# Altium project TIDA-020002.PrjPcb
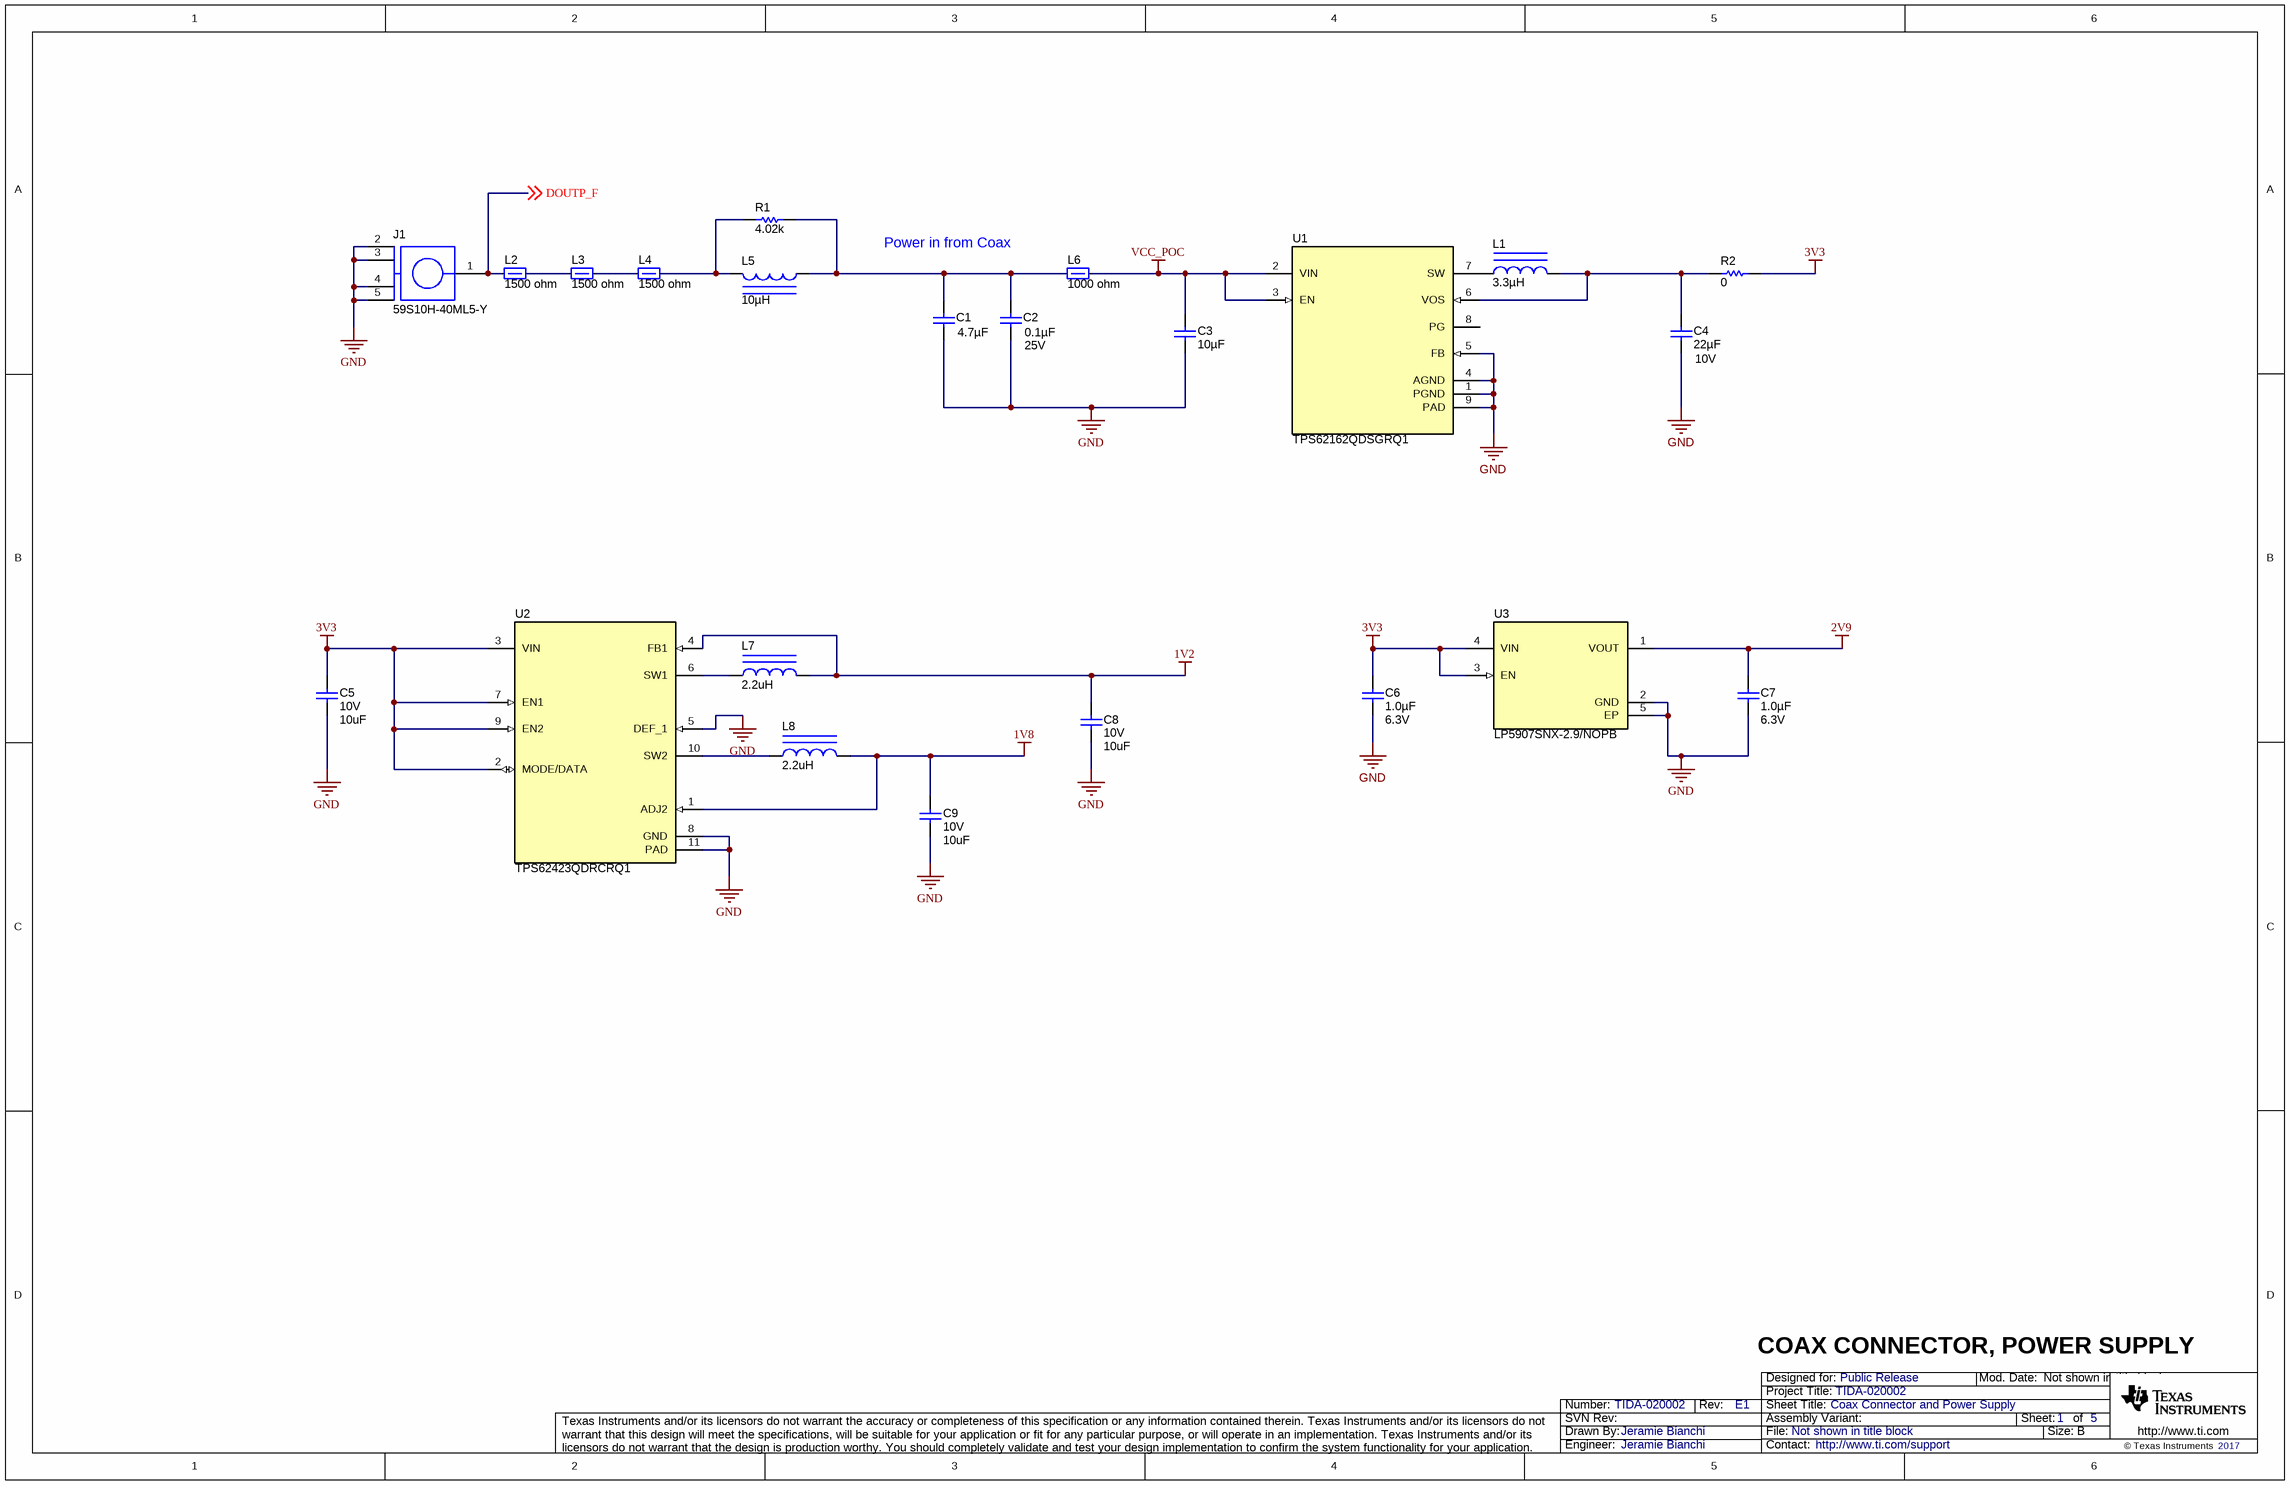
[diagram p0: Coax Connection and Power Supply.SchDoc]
TechSupport: http://www.ti.com/support; SCH_Rev: E1; PRJ_Title: TIDA-020002; PRJ_Number: TIDA-020002; PRJ_Engineer: Jeramie Bianchi; PRJ_Customer: Public Release; PCB_Rev: E1; PCB_Layout: Jeramie Bianchi; CopyrightYear: 2017
5 sheets, 104 parts. Net scope: global (net labels, ports and power ports of the same name join across sheets).
Board file: TIDA-020002.PcbDoc
Sheets:
  Coax Connection and Power Supply.SchDoc
  Imager.SchDoc
  Serializer.SchDoc
  HDWR.SchDoc
  Voltage Supervision.SchDoc

## Sheet Coax Connection and Power Supply.SchDoc: Coax Connector and Power Supply
size 431 x 279 mm; Date: Not shown in title block; ApprovedBy: Not shown in title block; CheckedBy: Not shown in title block; Author: Not shown in title block; CompanyName: Not shown in title block; DrawnBy: Jeramie Bianchi; Engineer: Not shown in title block; Organization: Not shown in title block; Address1: Not shown in title block; Address2: Not shown in title block; Address3: Not shown in title block; Address4: Not shown in title block; DocumentNumber: 1; Revision: Use project parameter SCH_Rev; SheetNumber: 1; SheetTotal: 5; PageSetup: Record=PageOptions¦CenterHorizontal=True¦CenterVertical=True¦PrintScale=0.62¦XCorrection=1.00¦YCorrection=1.00¦PrintKind=0¦BorderSize=5000000¦LeftOffset=0¦BottomOffset=0¦Orientation=2¦PaperLength=1000¦PaperWidth=1000¦Scale=100¦PaperSource=15¦PrintQuality=600¦MediaType=1¦DitherType=10¦PrintScaleMode=1¦PaperKind=Letter (8.5 x 11")¦PaperIndex=1

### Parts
C1  value 4.7µF  [0805L]  (hidden comment: CGA4J1X7R1E475M125AC)
C2  value 0.1µF  VDC_V: 25V  [0402L]  (hidden comment: C1005X7R1E104K050BB)
C3  ValueDisplayed: 10µF  [1206_190]  (hidden comment: C3216X7R1E106M160AE)
C4  ValueDisplayed: 22µF  VDC_V: 10V  [1206L]  (hidden comment: GRM31CR71A226KE15L)
C5  VDC_V: 10V  ValueDisplayed: 10uF  [0603S]  (hidden comment: GRM188Z71A106MA73D)
C6  value 1.0µF  VDC_V: 6.3V  [0402L]  (hidden comment: CL05B105KQ5NQNC)
C7  value 1.0µF  VDC_V: 6.3V  [0402L]  (hidden comment: CL05B105KQ5NQNC)
C8  VDC_V: 10V  ValueDisplayed: 10uF  [0603S]  (hidden comment: GRM188Z71A106MA73D)
C9  VDC_V: 10V  ValueDisplayed: 10uF  [0603S]  (hidden comment: GRM188Z71A106MA73D)
J1  59S10H-40ML5-Y  [59S10H-40ML5-Y]
L1  ValueDisplayed: 3.3µH  [XPL2010]  (hidden comment: XPL2010-332MLB)
L2  value 1500 ohm  [0603L]  (hidden comment: BLM18HE152SN1D)
L3  value 1500 ohm  [0603L]  (hidden comment: BLM18HE152SN1D)
L4  value 1500 ohm  [0603L]  (hidden comment: BLM18HE152SN1D)
L5  ValueDisplayed: 10µH  [LQH3NPZ_JR]  (hidden comment: LQH3NPZ100MJRL)
L6  value 1000 ohm  [0603L]  (hidden comment: BLM18AG102SN1D)
L7  ValueDisplayed: 2.2uH  [LQM2MPN_G0]  (hidden comment: LQM2MPN2R2NG0)
L8  ValueDisplayed: 2.2uH  [LQM2MPN_G0]  (hidden comment: LQM2MPN2R2NG0)
R1  ValueDisplayed: 4.02k  [0603L]  (hidden comment: CRCW06034K02FKEA)
R2  value 0  [0402S]  (hidden comment: CRCW04020000Z0ED)
U1  TPS62162QDSGRQ1  [DSG0008A]
U2  TPS62423QDRCRQ1  [DRC0010J]
U3  LP5907SNX-2.9/NOPB  [DQN0004A]

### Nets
1V2: C8.1 L7.2 U2.4(FB1)
1V8: C9.1 L8.2 U2.1(ADJ2)
2V9: C7.1 U3.1(VOUT)
3V3: C5.1 C6.1 R2.1 U2.2(MODE/DATA) U2.3(VIN) U2.7(EN1) U2.9(EN2) U3.3(EN) U3.4(VIN)
GND: C1.2 C2.2 C3.2 C4.2 C5.2 C6.2 C7.2 C8.2 C9.2 J1.2 J1.3 J1.4 J1.5 U1.1(PGND) U1.4(AGND) U1.5(FB) U1.9(PAD) U2.5(DEF_1) U2.8(GND) U2.11(PAD) U3.2(GND) U3.5(EP)
VCC_POC: C3.1 L6.2 U1.2(VIN) U1.3(EN)
DOUTP_F: J1.1 L2.1 ; off-sheet DOUTP_F
NetC1_1: C1.1 C2.1 L5.1 L6.1 R1.1
NetC4_1: C4.1 L1.2 R2.2 U1.6(VOS)
NetL1_1: L1.1 U1.7(SW)
NetL2_2: L2.2 L3.1
NetL3_2: L3.2 L4.1
NetL4_2: L4.2 L5.2 R1.2
NetL7_1: L7.1 U2.6(SW1)
NetL8_1: L8.1 U2.10(SW2)

Not connected (* = marked no-connect by the designer): U1 8(PG)

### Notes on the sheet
- (near L6) Power in from Coax
- COAX CONNECTOR, POWER SUPPLY

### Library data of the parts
C1 = C2012X7R1E474K: CAP, CERM, 4.7uF, 25V, +/-20%, X7R, 0805; Manufacturer: TDK Corporation; Tolerance_%: ±20%
C2 = C1005X7R1E103K: CAP, CERM, 0.1uF, 25V, +/-10%, X7R, 0402; Manufacturer: TDK Corporation; Tolerance_%: ±10%
C3 = C3216X7R1E106M160AE: CAP, CERM, 10 µF, 25 V,+/- 20%, X7R, 1206; Manufacturer: TDK; Polarized: N; CompType: Capacitor; Value: 10uF; U/M: EA; Cap_F: 0.00001; Tolerance_%: 20; VDC_V: 25; Value2: 25V; TaMin_C: -55; TaMax_C: 125; Cap_Case: 1206; SizeArea_mm2: 5.12; SizeAreaWB_mm2: 10.92; SizeX_mm: 3.2; SizeY_mm: 1.6; SizeZ_mm: 1.9; AEC Category: Q200; Green_Lifecycle: Active; Green_REACh: Passed
C4 = GRM31CR71A226KE15L: CAP, CERM, 22uF, 10V, +/-10%, X7R, 1206; Manufacturer: MuRata; Polarized: N; CompType: Capacitor; U/M: EA; Cap_F: 0.000022; Tolerance_%: 10; Value1: Unknown; TaMin_C: -55; TaMax_C: 125; Cap_Case: 1206
C5 C8 C9 = CMP-0007497-5: CAP, CERM, 10 uF, 10 V, +/- 20%, X7R, 0603; Manufacturer: MuRata; TaMin_C: -55°C; Polarized: N; SizeAreaWB_mm2: 4.68; Value1: Unknown; U/M: EA; Value: 10uF; TaMax_C: 125°C; SizeZ_mm: 1; SizeX_mm: 1.6; SizeY_mm: 0.8; Cap_Case: 0603; SizeArea_mm2: 1.28; CompType: Capacitor; Cap_F: 10µF; AEC Category: Q200
C6 C7 = Capacitor: CAP CER 1UF 6.3V 10% X7R 0402; Manufacturer: Samsung Electro-Mechanics America, Inc; Polarized: N; U/M: EA
J1 = 59S10H-40ML5-Y: Straight Plug PCB; Manufacturer: Rosenberger; SymbolVersion: use current date i.e. 2008-05-20; SymbolCreator: Use a-id; CompType: SMA connector; U/M: EA, IN, or GM
L1 = XPL2010-332MLB: Inductor, Shielded, Composite, 3.3 µH, 1.05 A, 0.21 ohm, SMD; Manufacturer: Coilcraft; Value: 3.3uH; Ind_H: 3.3E-6; Imax_A: 1.05; Irms: 1.1A @ 40C rise; Isat: 1.05A @ 30% inductance drop; DCR_ohm: 0.21; Value2: 1.05A; SizeAreaWB_mm2: 8.7; SizeArea_mm2: 3.8; SizeX_mm: 2; SizeY_mm: 1.9; SizeZ_mm: 1; AEC Category: Q200; Green_Lifecycle: Not Set; Green_REACh: Incomplete
L2 L3 = BLM18HE152SN1D: Ferrite Bead, 1500 ohm @ 100 MHz, 0.5 A, 0603; Manufacturer: MuRata; Imax_A: 0.5; Value1: 0.5 ohm; Value2: 0.5A; ZTyp@100MHz_Ohm: 1500; SizeAreaWB_mm2: 4.68; SizeArea_mm2: 1.28; SizeX_mm: 1.6; SizeY_mm: 0.8; SizeZ_mm: 1
L4 = BLM18HE152SN1D: Ferrite Bead, 1500 ohm @ 100 MHz, 0.5 A, 0603; Manufacturer: MuRata; Value1: 0.5 ohm; Value2: 0.5A; SizeArea_mm2: 1.28; SizeX_mm: 1.6; SizeY_mm: 0.8; SizeZ_mm: 1; Imax_A: 0.5; SizeAreaWB_mm2: 4.68; ZTyp@100MHz_Ohm: 1500
L5 = LQH3NPZ100MJRL: Inductor, Wirewound, Ferrite, 10 µH, 0.81 A, 0.288 ohm, AEC-Q200 Grade 1, SMD; Manufacturer: MuRata; Value: 10uH; Ind_H: 10.0E-6; Imax_A: 0.81; Irms: 1.2A @ 40C rise; Isat: 0.81A @ 30% inductance drop; DCR_ohm: 0.288; Value2: 0.81A; SizeAreaWB_mm2: 16; SizeArea_mm2: 9; SizeX_mm: 3; SizeZ_mm: 1.2; AEC Category: Q200; AEC Qualified: Y; AEC Grade: 1
L6 = BLM18AG102SN1D: Ferrite Bead, 1000 ohm @ 100 MHz, 0.4 A, 0603; Manufacturer: MuRata; Imax_A: 0.4; DCR_ohm: 0.5; Value1: 0.5 ohm; Value2: 0.4A; ZTyp@100MHz_Ohm: 1000
L7 L8 = CMP-0058761-1: Inductor, Multilayer, Ferrite, 2.2 uH, 1.2 A, 0.11 ohm, SMD; Manufacturer: MuRata; Irms: 1.2A @ 40C rise; SizeAreaWB_mm2: 7.8; DCR_ohm: 1.1d; Value: 2.2uH; Imax_A: 1.2A; SizeZ_mm: 1; SizeX_mm: 2; SizeY_mm: 1.6; SizeArea_mm2: 3.2; Ind_H: 2.2µH; AEC Qualified: N; AEC Category: Q200
R1 = CRCW06034K02FKEA: RES, 4.02 k, 1%, 0.1 W, 0603; Manufacturer: Vishay-Dale; CompType: Resistor; Value: 4.02k; Res_ohm: 4020; Value_Code: 4k02; Tolerance_%: 1; Power_W: 0.1; Value2: 0.1W; VDC_V: 75; TempCo: 100 ppm/C; EIA_Code: E96; U/M: EA
R2 = CRCW04020000Z0ED: RES, 0 ohm, 5%, 0.063W, 0402; Manufacturer: Vishay-Dale; CompType: Resistor; Value_Code: 0000; Tolerance_%: 5; Power_W: 0.063; VDC_V: 50; TempCo: 200 ppm/C; EIA_Code: E24; U/M: EA
U1 = TPS62162QDSGRQ1: 3V-17V 1A Automotive Step-Down Converters in 2x2SON, DSG0008A (WSON-8); Manufacturer: Texas Instruments; Alternate PartNumber: TPS62162QDSGTQ1; SymbolCreator: Altium; SizeArea_mm2: 4; SizeAreaWB_mm2: 9; SizeX_mm: 2; SizeZ_mm: 0.8; CompType: IC; U/M: EA
U2 = CMP-0074043-2: Automotive 2.5V to 6V, 2.25MHz Fixed Frequency Dual (800mA/800mA) Buck Converter, DRC0010J (VSON-10); Alternate Manufacturer: Texas Instruments; Green_Lifecycle: Active; SizeAreaWB_mm2: 16.0; Green_REACh: Passed; U/M: EA; SizeZ_mm: 1.0; SizeX_mm: 3.0; SizeArea_mm2: 9.0; CompType: IC
U3 = CMP-0066023-1: 250-mA Ultra-Low-Noise, Low-IQ LDO, DQN0004A (X2SON-4); Alternate Manufacturer: Texas Instruments; SizeAreaWB_mm2: 4.0; U/M: EA; SizeZ_mm: 0.4; SizeX_mm: 1.0; CompType: IC

## Sheet Imager.SchDoc: Image Sensor
size 431 x 279 mm; Date: Not shown in title block; ApprovedBy: Not shown in title block; CheckedBy: Not shown in title block; Author: Not shown in title block; CompanyName: Not shown in title block; DrawnBy: Jeramie Bianchi; Engineer: Not shown in title block; Organization: Not shown in title block; Address1: Not shown in title block; Address2: Not shown in title block; Address3: Not shown in title block; Address4: Not shown in title block; DocumentNumber: 2; Revision: Use project parameter SCH_Rev; SheetNumber: 3; SheetTotal: 5; PageSetup: Record=PageOptions¦CenterHorizontal=True¦CenterVertical=True¦PrintScale=0.96¦XCorrection=1.00¦YCorrection=1.00¦PrintKind=0¦BorderSize=5000000¦LeftOffset=0¦BottomOffset=0¦Orientation=2¦PaperLength=4318¦PaperWidth=2794¦Scale=100¦PaperSource=15¦PrintQuality=600¦MediaType=1¦DitherType=10¦PrintScaleMode=1¦PaperKind=Tabloid (11 x 17")¦PaperIndex=17
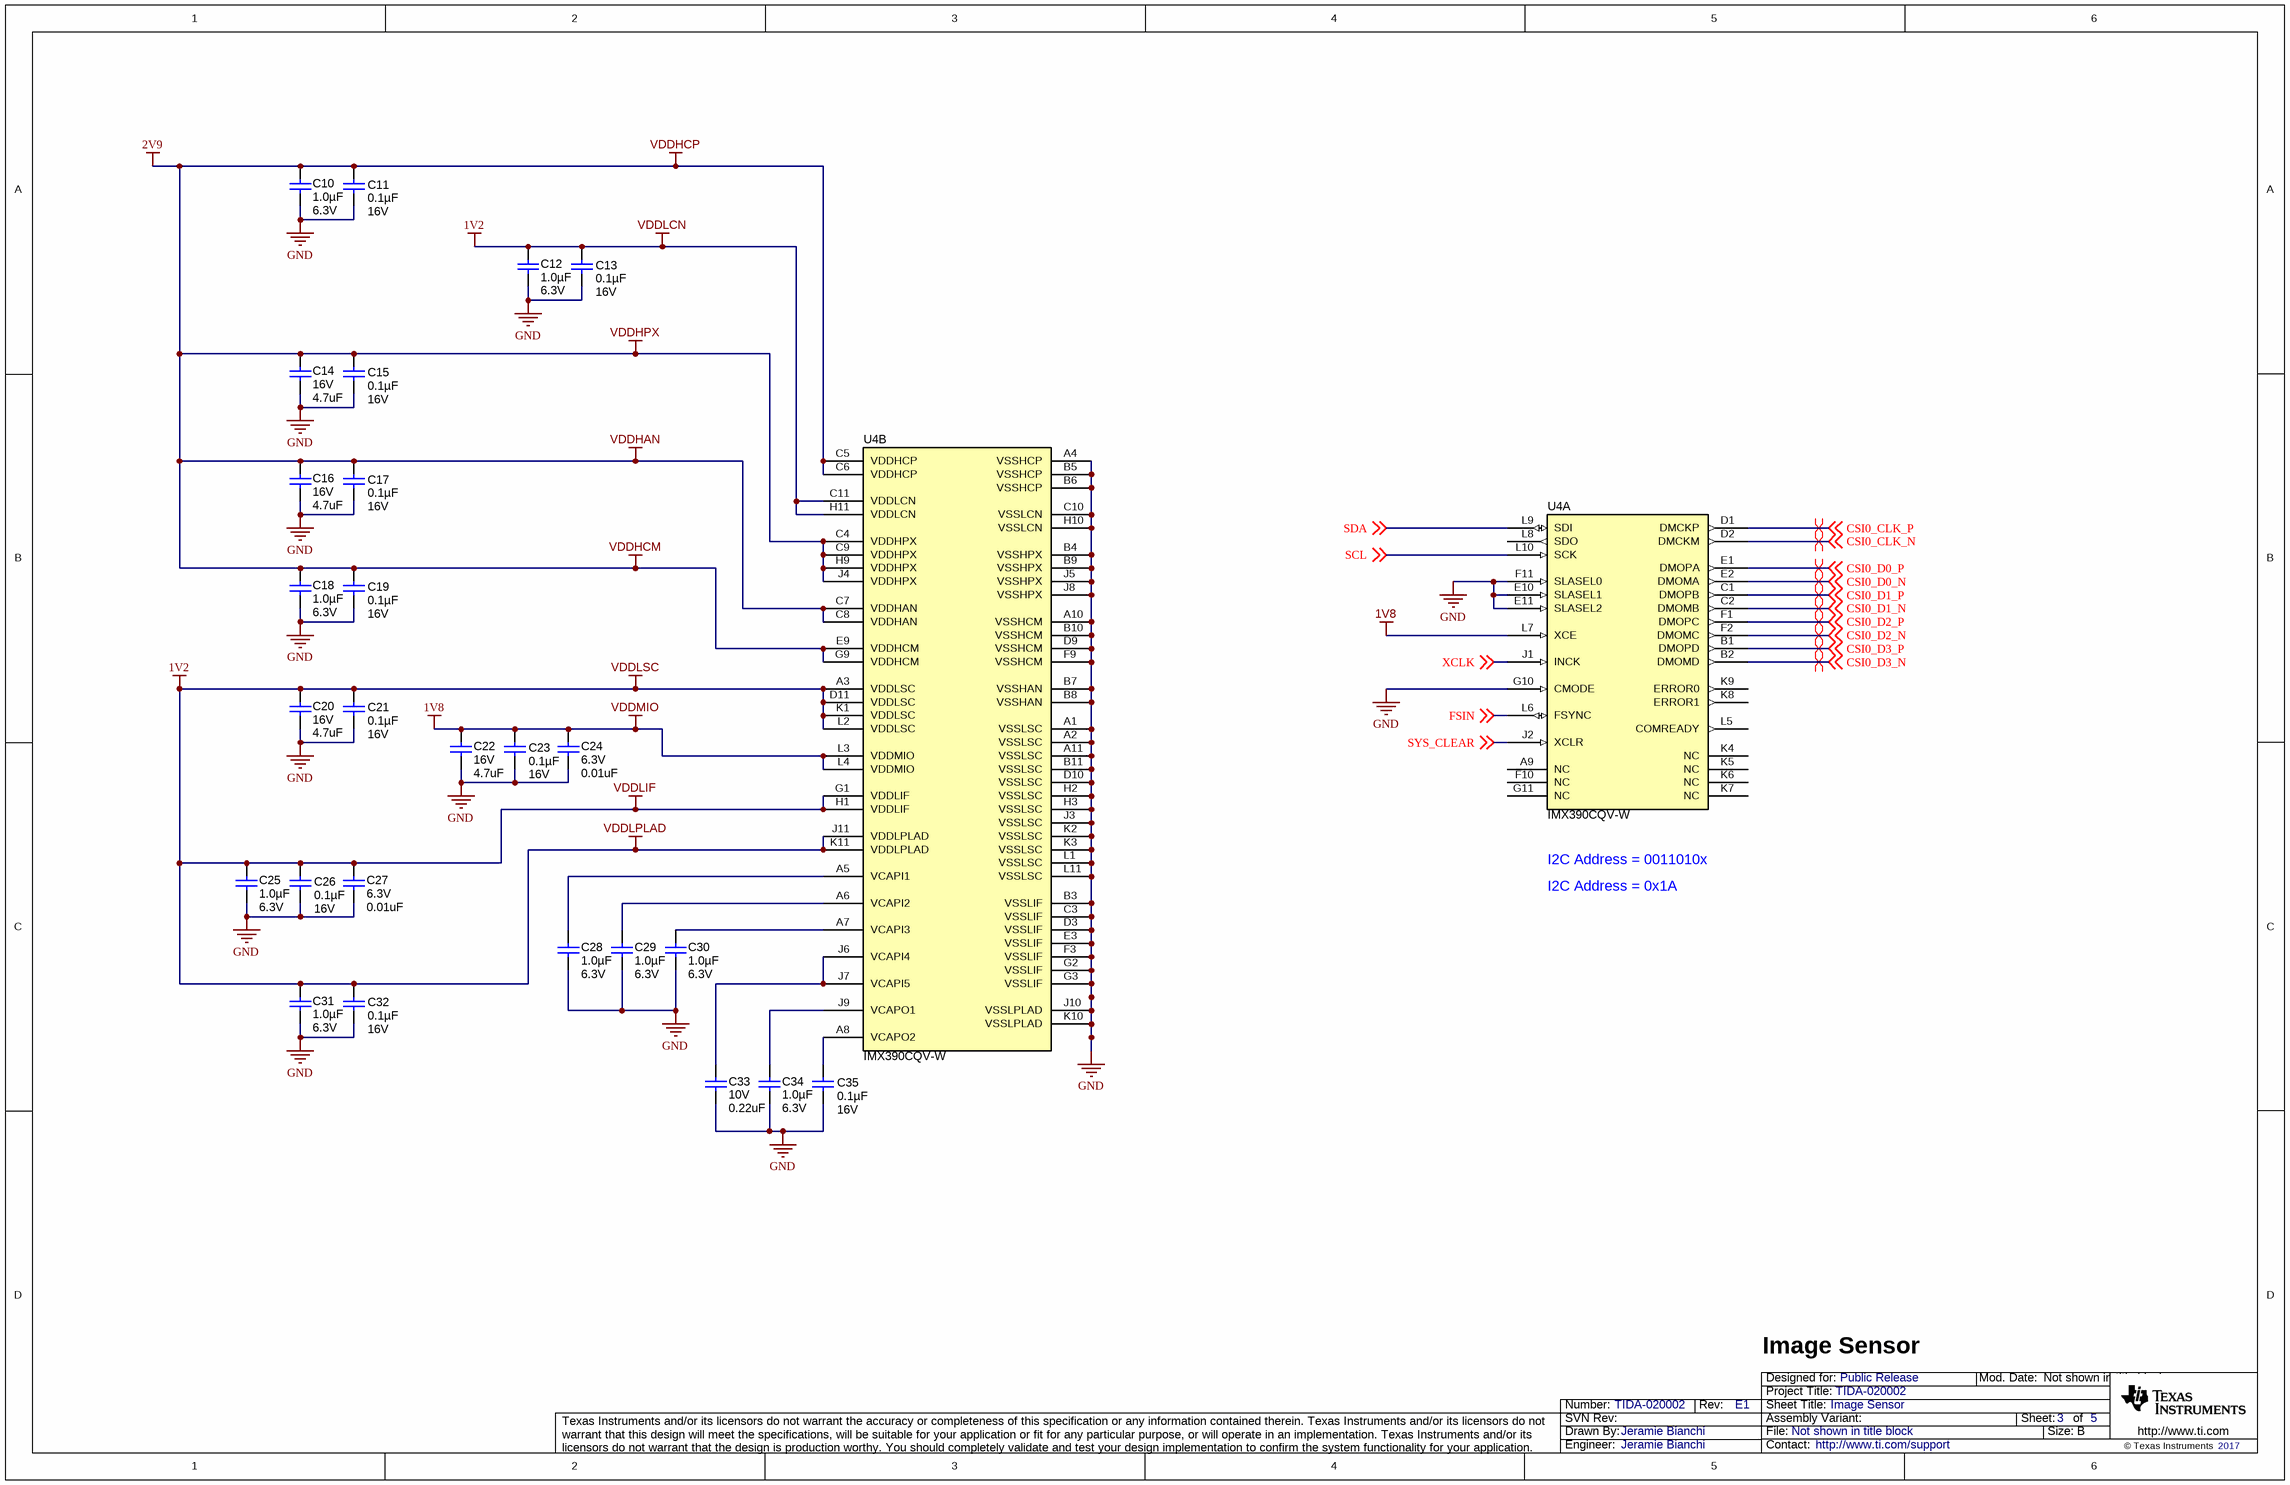
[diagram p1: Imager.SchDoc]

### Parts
C10  value 1.0µF  VDC_V: 6.3V  [0402L]  (hidden comment: CL05B105KQ5NQNC)
C11  ValueDisplayed: 0.1µF  Value2: 16V  [0402S]  (hidden comment: 0402YC104KAT2A)
C12  value 1.0µF  VDC_V: 6.3V  [0402L]  (hidden comment: CL05B105KQ5NQNC)
C13  ValueDisplayed: 0.1µF  Value2: 16V  [0402S]  (hidden comment: 0402YC104KAT2A)
C14  VDC_V: 16V  ValueDisplayed: 4.7uF  [0603S]  (hidden comment: GRM188Z71C475KE21D)
C15  ValueDisplayed: 0.1µF  Value2: 16V  [0402S]  (hidden comment: 0402YC104KAT2A)
C16  VDC_V: 16V  ValueDisplayed: 4.7uF  [0603S]  (hidden comment: GRM188Z71C475KE21D)
C17  ValueDisplayed: 0.1µF  Value2: 16V  [0402S]  (hidden comment: 0402YC104KAT2A)
C18  value 1.0µF  VDC_V: 6.3V  [0402L]  (hidden comment: CL05B105KQ5NQNC)
C19  ValueDisplayed: 0.1µF  Value2: 16V  [0402S]  (hidden comment: 0402YC104KAT2A)
C20  VDC_V: 16V  ValueDisplayed: 4.7uF  [0603S]  (hidden comment: GRM188Z71C475KE21D)
C21  ValueDisplayed: 0.1µF  Value2: 16V  [0402S]  (hidden comment: 0402YC104KAT2A)
C22  VDC_V: 16V  ValueDisplayed: 4.7uF  [0603S]  (hidden comment: GRM188Z71C475KE21D)
C23  ValueDisplayed: 0.1µF  Value2: 16V  [0402S]  (hidden comment: 0402YC104KAT2A)
C24  VDC_V: 6.3V  ValueDisplayed: 0.01uF  [0402S]  (hidden comment: GRM155R70J103KA01D)
C25  value 1.0µF  VDC_V: 6.3V  [0402L]  (hidden comment: CL05B105KQ5NQNC)
C26  ValueDisplayed: 0.1µF  Value2: 16V  [0402S]  (hidden comment: 0402YC104KAT2A)
C27  VDC_V: 6.3V  ValueDisplayed: 0.01uF  [0402S]  (hidden comment: GRM155R70J103KA01D)
C28  value 1.0µF  VDC_V: 6.3V  [0402L]  (hidden comment: CL05B105KQ5NQNC)
C29  value 1.0µF  VDC_V: 6.3V  [0402L]  (hidden comment: CL05B105KQ5NQNC)
C30  value 1.0µF  VDC_V: 6.3V  [0402L]  (hidden comment: CL05B105KQ5NQNC)
C31  value 1.0µF  VDC_V: 6.3V  [0402L]  (hidden comment: CL05B105KQ5NQNC)
C32  ValueDisplayed: 0.1µF  Value2: 16V  [0402S]  (hidden comment: 0402YC104KAT2A)
C33  VDC_V: 10V  ValueDisplayed: 0.22uF  [0402S]  (hidden comment: GRM155R71A224KE01D)
C34  value 1.0µF  VDC_V: 6.3V  [0402L]  (hidden comment: CL05B105KQ5NQNC)
C35  ValueDisplayed: 0.1µF  Value2: 16V  [0402S]  (hidden comment: 0402YC104KAT2A)
U4  IMX390CQV-W  [BGA-96]  (parts A,B of 2)

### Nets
1V2: C12.1 C13.1 C20.1 C21.1 C25.1 C26.1 C27.1 C31.1 C32.1 U4.A3(VDDLSC) U4.C11(VDDLCN) U4.D11(VDDLSC) U4.G1(VDDLIF) U4.H1(VDDLIF) U4.H11(VDDLCN) U4.J11(VDDLPLAD) U4.K1(VDDLSC) U4.K11(VDDLPLAD) U4.L2(VDDLSC)  [also labelled VDDLCN, VDDLIF, VDDLPLAD, VDDLSC]
1V8: C22.1 C23.1 C24.1 U4.L3(VDDMIO) U4.L4(VDDMIO) U4.L7(XCE)  [also labelled VDDMIO]
2V9: C10.1 C11.1 C14.1 C15.1 C16.1 C17.1 C18.1 C19.1 U4.C4(VDDHPX) U4.C5(VDDHCP) U4.C6(VDDHCP) U4.C7(VDDHAN) U4.C8(VDDHAN) U4.C9(VDDHPX) U4.E9(VDDHCM) U4.G9(VDDHCM) U4.H9(VDDHPX) U4.J4(VDDHPX)  [also labelled VDDHAN, VDDHCM, VDDHCP, VDDHPX]
GND: C10.2 C11.2 C12.2 C13.2 C14.2 C15.2 C16.2 C17.2 C18.2 C19.2 C20.2 C21.2 C22.2 C23.2 C24.2 C25.2 C26.2 C27.2 C28.2 C29.2 C30.2 C31.2 C32.2 C33.2 C34.2 C35.2 U4.A1(VSSLSC) U4.A2(VSSLSC) U4.A4(VSSHCP) U4.A10(VSSHCM) U4.A11(VSSLSC) U4.B3(VSSLIF) U4.B4(VSSHPX) U4.B5(VSSHCP) U4.B6(VSSHCP) U4.B7(VSSHAN) U4.B8(VSSHAN) U4.B9(VSSHPX) U4.B10(VSSHCM) U4.B11(VSSLSC) U4.C3(VSSLIF) U4.C10(VSSLCN) U4.D3(VSSLIF) U4.D9(VSSHCM) U4.D10(VSSLSC) U4.E3(VSSLIF) U4.E10(SLASEL1) U4.E11(SLASEL2) U4.F3(VSSLIF) U4.F9(VSSHCM) U4.F11(SLASEL0) U4.G2(VSSLIF) U4.G3(VSSLIF) U4.G10(CMODE) U4.H2(VSSLSC) U4.H3(VSSLSC) U4.H10(VSSLCN) U4.J3(VSSLSC) U4.J5(VSSHPX) U4.J8(VSSHPX) U4.J10(VSSLPLAD) U4.K2(VSSLSC) U4.K3(VSSLSC) U4.K10(VSSLPLAD) U4.L1(VSSLSC) U4.L11(VSSLSC)
CSI0_CLK_N: U4.D2(DMCKM) ; off-sheet CSI0_CLK_N
CSI0_CLK_P: U4.D1(DMCKP) ; off-sheet CSI0_CLK_P
CSI0_D0_N: U4.E2(DMOMA) ; off-sheet CSI0_D0_N
CSI0_D0_P: U4.E1(DMOPA) ; off-sheet CSI0_D0_P
CSI0_D1_N: U4.C2(DMOMB) ; off-sheet CSI0_D1_N
CSI0_D1_P: U4.C1(DMOPB) ; off-sheet CSI0_D1_P
CSI0_D2_N: U4.F2(DMOMC) ; off-sheet CSI0_D2_N
CSI0_D2_P: U4.F1(DMOPC) ; off-sheet CSI0_D2_P
CSI0_D3_N: U4.B2(DMOMD) ; off-sheet CSI0_D3_N
CSI0_D3_P: U4.B1(DMOPD) ; off-sheet CSI0_D3_P
FSIN: U4.L6(FSYNC) ; off-sheet FSIN
SCL: U4.L10(SCK) ; off-sheet SCL
SDA: U4.L9(SDI) ; off-sheet SDA
SYS_CLEAR: U4.J2(XCLR) ; off-sheet SYS_CLEAR
XCLK: U4.J1(INCK) ; off-sheet XCLK
NetC28_1: C28.1 U4.A5(VCAPI1)
NetC29_1: C29.1 U4.A6(VCAPI2)
NetC30_1: C30.1 U4.A7(VCAPI3)
NetC33_1: C33.1 U4.J6(VCAPI4) U4.J7(VCAPI5)
NetC34_1: C34.1 U4.J9(VCAPO1)
NetC35_1: C35.1 U4.A8(VCAPO2)

Not connected (* = marked no-connect by the designer): U4 A9(NC) F10(NC) G11(NC) K4(NC) K5(NC) K6(NC) K7(NC) K8(ERROR1) K9(ERROR0) L5(COMREADY) L8(SDO)

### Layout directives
differential pair: CSI0_CLK_N, CSI0_CLK_P, CSI0_D0_N, CSI0_D0_P, CSI0_D1_N, CSI0_D1_P, CSI0_D2_N, CSI0_D2_P, CSI0_D3_N, CSI0_D3_P

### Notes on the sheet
- I2C Address = 0011010x
- I2C Address = 0x1A
- Image Sensor

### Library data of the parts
C10 C12 C18 C25 C28-C31 C34 = Capacitor: as C6 on sheet Coax Connection and Power Supply
C11 C13 C15 C17 C19 C21 C23 C26 C32 C35 = 0402YC104KAT2A: CAP, CERM, 0.1 µF, 16 V, +/- 10%, X7R, 0402; Manufacturer: AVX; Polarized: N; CompType: Capacitor; Value: 0.1uF; U/M: EA; Cap_F: 0.0000001; Tolerance_%: 10; Value1: Unknown; VDC_V: 16; TaMin_C: -55; TaMax_C: 125; Cap_Case: 0402; SizeArea_mm2: 0.5; SizeAreaWB_mm2: 3; SizeX_mm: 1; SizeZ_mm: 0.6; AEC Category: Q200
C14 C16 C20 C22 = CMP-0064936-4: CAP, CERM, 4.7 uF, 16 V,+/- 10%, X7R, 0603; Manufacturer: MuRata; TaMin_C: -55°C; Polarized: N; SizeAreaWB_mm2: 4.68; Value1: Unknown; U/M: EA; Value: 4.7uF; TaMax_C: 125°C; SizeZ_mm: 1; SizeX_mm: 1.6; SizeY_mm: 0.8; Cap_Case: 0603; SizeArea_mm2: 1.28; CompType: Capacitor; Cap_F: 4.7µF; AEC Category: Q200
C24 C27 = CMP-0006622-2: CAP, CERM, 0.01 uF, 6.3 V, +/- 10%, X7R, 0402; Manufacturer: MuRata; TaMin_C: -55°C; Polarized: N; SizeAreaWB_mm2: 3; Value1: Unknown; U/M: EA; Value: 0.01uF; TaMax_C: 125°C; SizeZ_mm: 0.6; SizeX_mm: 1; SizeY_mm: 0.5; Cap_Case: 0402; CompType: Capacitor; Cap_F: 10nF; AEC Category: Q200
C33 = CMP-0006630-2: CAP, CERM, 0.22 uF, 10 V, +/- 10%, X7R, 0402; Manufacturer: MuRata; TaMin_C: -55°C; Polarized: N; SizeAreaWB_mm2: 3; Value1: Unknown; U/M: EA; Value: 0.22uF; TaMax_C: 125°C; SizeZ_mm: 0.6; SizeX_mm: 1; SizeY_mm: 0.5; Cap_Case: 0402; CompType: Capacitor; Cap_F: 220nF; AEC Category: Q200
U4 = CMP-0078540-1: Diagonal 6.67mm (Type 1/2.7) CMOS Solid-sate Image Sensor with Square Pixel and RGGB Filter Array, BGA-96; Manufacturer: Sony; SizeArea_mm2: 106; SizeAreaWB_mm2: 151.2; SizeY_mm: 10; SizeZ_mm: 1.6; SizeX_mm: 10.6

## Sheet Serializer.SchDoc: Serializer
size 431 x 279 mm; Date: Not shown in title block; ApprovedBy: Not shown in title block; CheckedBy: Not shown in title block; Author: Not shown in title block; CompanyName: Not shown in title block; DrawnBy: Jeramie Bianchi; Engineer: Not shown in title block; Organization: Not shown in title block; Address1: Not shown in title block; Address2: Not shown in title block; Address3: Not shown in title block; Address4: Not shown in title block; DocumentNumber: 3; Revision: Use project parameter SCH_Rev; SheetNumber: 4; SheetTotal: 5; PageSetup: Record=PageOptions¦CenterHorizontal=True¦CenterVertical=True¦PrintScale=0.64¦XCorrection=1.00¦YCorrection=1.00¦PrintKind=0¦BorderSize=5000000¦LeftOffset=0¦BottomOffset=0¦Orientation=2¦PaperLength=4318¦PaperWidth=2794¦Scale=100¦PaperSource=15¦PrintQuality=600¦MediaType=1¦DitherType=10¦PrintScaleMode=1¦PaperKind=Tabloid (11 x 17")¦PaperIndex=17
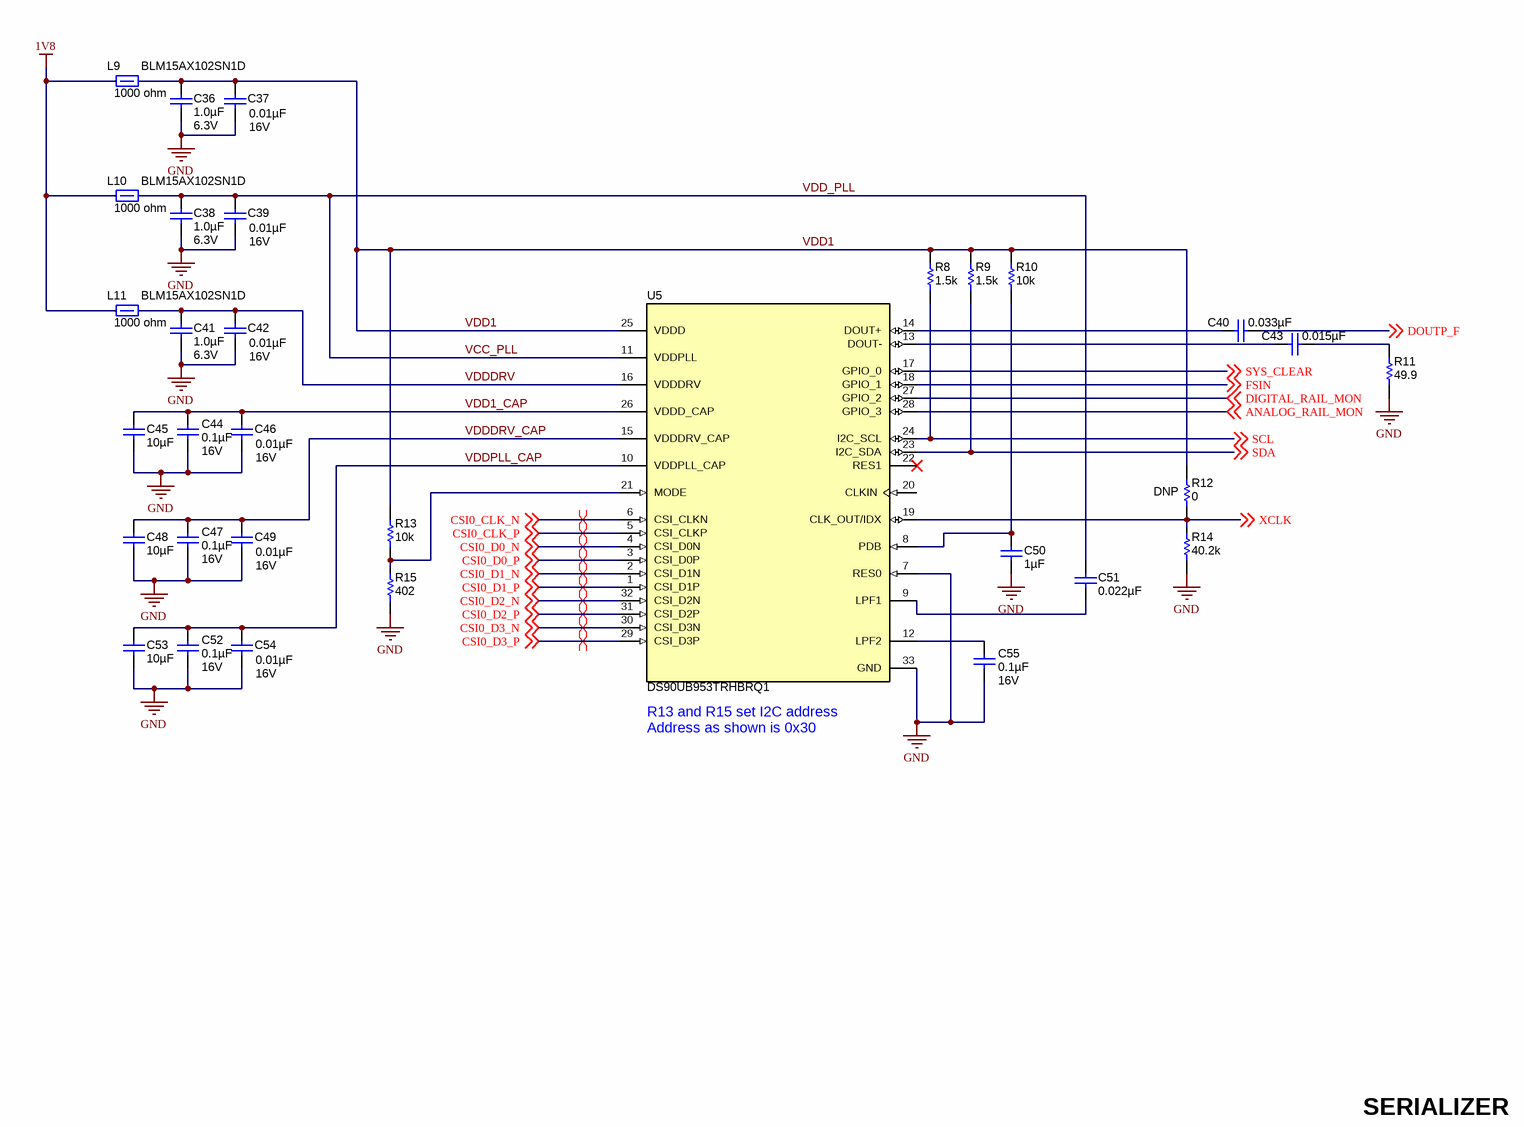
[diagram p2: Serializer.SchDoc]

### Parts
C36  value 1.0µF  VDC_V: 6.3V  [0402L]  (hidden comment: CL05B105KQ5NQNC)
C37  ValueDisplayed: 0.01µF  Value2: 16V  [0402S]  (hidden comment: GRM155R71C103KA01D)
C38  value 1.0µF  VDC_V: 6.3V  [0402L]  (hidden comment: CL05B105KQ5NQNC)
C39  ValueDisplayed: 0.01µF  Value2: 16V  [0402S]  (hidden comment: GRM155R71C103KA01D)
C40  ValueDisplayed: 0.033µF  [0402S]  (hidden comment: CGA2B3X7R1H333K050BB)
C41  value 1.0µF  VDC_V: 6.3V  [0402L]  (hidden comment: CL05B105KQ5NQNC)
C42  ValueDisplayed: 0.01µF  Value2: 16V  [0402S]  (hidden comment: GRM155R71C103KA01D)
C43  ValueDisplayed: 0.015µF  [0402S]  (hidden comment: CGA2B3X7R1H153K050BB)
C44  ValueDisplayed: 0.1µF  Value2: 16V  [0402S]  (hidden comment: 0402YC104KAT2A)
C45  ValueDisplayed: 10µF  [0603S]  (hidden comment: GRM188Z71A106MA73D)
C46  ValueDisplayed: 0.01µF  Value2: 16V  [0402S]  (hidden comment: GRM155R71C103KA01D)
C47  ValueDisplayed: 0.1µF  Value2: 16V  [0402S]  (hidden comment: 0402YC104KAT2A)
C48  ValueDisplayed: 10µF  [0603S]  (hidden comment: GRM188Z71A106MA73D)
C49  ValueDisplayed: 0.01µF  Value2: 16V  [0402S]  (hidden comment: GRM155R71C103KA01D)
C50  ValueDisplayed: 1µF  [0402S]  (hidden comment: GRM155R70J105MA12D)
C51  ValueDisplayed: 0.022µF  [0402S]  (hidden comment: GRM155R70J223KA01D)
C52  ValueDisplayed: 0.1µF  Value2: 16V  [0402S]  (hidden comment: 0402YC104KAT2A)
C53  ValueDisplayed: 10µF  [0603S]  (hidden comment: GRM188Z71A106MA73D)
C54  ValueDisplayed: 0.01µF  Value2: 16V  [0402S]  (hidden comment: GRM155R71C103KA01D)
C55  ValueDisplayed: 0.1µF  Value2: 16V  [0402S]  (hidden comment: 0402YC104KAT2A)
L9  value 1000 ohm  [0402S]  (hidden comment: BLM15AX102SN1D)
L10  value 1000 ohm  [0402S]  (hidden comment: BLM15AX102SN1D)
L11  value 1000 ohm  [0402S]  (hidden comment: BLM15AX102SN1D)
R8  ValueDisplayed: 1.5k  [0402S]  (hidden comment: CRCW04021K50JNED)
R9  ValueDisplayed: 1.5k  [0402S]  (hidden comment: CRCW04021K50JNED)
R10  value 10k  [0402S]  (hidden comment: CRCW040210K0JNED)
R11  value 49.9  [0402L]  (hidden comment: CRCW040249R9FKED)
R12  DNP  ValueDisplayed: 0  [0402S]  (no BOM)
R13  value 10k  [0402S]  (hidden comment: CRCW040210K0JNED)
R14  ValueDisplayed: 40.2k  [0402S]  (hidden comment: CRCW040240K2FKED)
R15  ValueDisplayed: 402  [0402S]  (hidden comment: CRCW0402402RFKED)
U5  DS90UB953TRHBRQ1  [RHB0032P]

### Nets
1V8: L9.1 L10.1 L11.1
GND: C36.2 C37.2 C38.2 C39.2 C41.2 C42.2 C44.2 C45.1 C46.2 C47.2 C48.1 C49.2 C50.2 C52.2 C53.1 C54.2 C55.2 R11.1 R14.1 R15.1 U5.7(RES0) U5.33(GND)
ANALOG_RAIL_MON: U5.28(GPIO_3) ; off-sheet ANALOG_RAIL_MON
CSI0_CLK_N: U5.6(CSI_CLKN) ; off-sheet CSI0_CLK_N
CSI0_CLK_P: U5.5(CSI_CLKP) ; off-sheet CSI0_CLK_P
CSI0_D0_N: U5.4(CSI_D0N) ; off-sheet CSI0_D0_N
CSI0_D0_P: U5.3(CSI_D0P) ; off-sheet CSI0_D0_P
CSI0_D1_N: U5.2(CSI_D1N) ; off-sheet CSI0_D1_N
CSI0_D1_P: U5.1(CSI_D1P) ; off-sheet CSI0_D1_P
CSI0_D2_N: U5.32(CSI_D2N) ; off-sheet CSI0_D2_N
CSI0_D2_P: U5.31(CSI_D2P) ; off-sheet CSI0_D2_P
CSI0_D3_N: U5.30(CSI_D3N) ; off-sheet CSI0_D3_N
CSI0_D3_P: U5.29(CSI_D3P) ; off-sheet CSI0_D3_P
DIGITAL_RAIL_MON: U5.27(GPIO_2) ; off-sheet DIGITAL_RAIL_MON
DOUTP_F: C40.1 ; off-sheet DOUTP_F
FSIN: U5.18(GPIO_1) ; off-sheet FSIN
SCL: R8.1 U5.24(I2C_SCL) ; off-sheet SCL
SDA: R9.1 U5.23(I2C_SDA) ; off-sheet SDA
SYS_CLEAR: U5.17(GPIO_0) ; off-sheet SYS_CLEAR
VCC_PLL: C38.1 C39.1 C51.1 L10.2 U5.11(VDDPLL)  [also labelled VDD_PLL]
VDD1: C36.1 C37.1 L9.2 R8.2 R9.2 R10.2 R12.2 R13.2 U5.25(VDDD)
VDD1_CAP: C44.1 C45.2 C46.1 U5.26(VDDD_CAP)
VDDDRV: C41.1 C42.1 L11.2 U5.16(VDDDRV)
VDDDRV_CAP: C47.1 C48.2 C49.1 U5.15(VDDDRV_CAP)
VDDPLL_CAP: C52.1 C53.2 C54.1 U5.10(VDDPLL_CAP)
XCLK: R12.1 R14.2 U5.19(CLK_OUT/IDX) ; off-sheet XCLK
NetC40_2: C40.2 U5.14(DOUT+)
NetC43_1: C43.1 R11.2
NetC43_2: C43.2 U5.13(DOUT-)
NetC50_1: C50.1 R10.1 U5.8(PDB)
NetC51_2: C51.2 U5.9(LPF1)
NetC55_1: C55.1 U5.12(LPF2)
NetR13_1: R13.1 R15.2 U5.21(MODE)

Not connected (* = marked no-connect by the designer): U5 20(CLKIN) 22(RES1)*

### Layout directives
differential pair: CSI0_CLK_N, CSI0_CLK_P, CSI0_D0_N, CSI0_D0_P, CSI0_D1_N, CSI0_D1_P, CSI0_D2_N, CSI0_D2_P, CSI0_D3_N, CSI0_D3_P

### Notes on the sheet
- (near U5) R13 and R15 set I2C address
  Address as shown is 0x30
- SERIALIZER

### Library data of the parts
C36 C38 C41 = Capacitor: as C6 on sheet Coax Connection and Power Supply
C37 C39 C42 C46 C49 C54 = GRM155R71C103KA01D: CAP, CERM, 0.01uF, 16V, +/-10%, X7R, 0402; Manufacturer: MuRata; Polarized: N; CompType: Capacitor; U/M: EA; Cap_F: 0.00000001; Tolerance_%: 10; Value1: Unknown; VDC_V: 16; TaMin_C: -55; TaMax_C: 125; Cap_Case: 0402
C40 = CGA2B3X7R1H333K050BB: CAP, CERM, 0.033 µF, 50 V, +/- 10%, X7R, 0402; Manufacturer: TDK; Polarized: N; CompType: Capacitor; Value: 0.033uF; U/M: EA; Cap_F: 0.000000033; Tolerance_%: 10; Value1: Unknown; VDC_V: 50; Value2: 50V; TaMin_C: -55; TaMax_C: 125; Cap_Case: 0402
C43 = CGA2B3X7R1H153K050BB: CAP, CERM, 0.015 µF, 50 V, +/- 10%, X7R, AEC-Q200 Grade 1, 0402; Manufacturer: TDK; Polarized: N; CompType: Capacitor; Value: 0.015uF; U/M: EA; Cap_F: 0.000000015; Tolerance_%: 10; ESR_ohm: 0.2162; Value1: 0.2162 ohm; VDC_V: 50; Value2: 50V; IRMS_A: 0.379389; TaMin_C: -55; TaMax_C: 125; Cap_Case: 0402; SizeArea_mm2: 0.5; SizeAreaWB_mm2: 3; SizeX_mm: 1; SizeZ_mm: 0.6; AEC Category: Q200; AEC Qualified: Y
C44 C47 C52 C55 = 0402YC104KAT2A: as C11 on sheet Imager
C45 C48 C53 = GRM188Z71A106MA73D: CAP, CERM, 10 µF, 10 V,+/- 20%, X7R, 0603; Manufacturer: MuRata; Polarized: N; CompType: Capacitor; Value: 10uF; U/M: EA; Cap_F: 0.00001; Tolerance_%: 20; VDC_V: 10; Value2: 10V; TaMin_C: -55; TaMax_C: 125; Cap_Case: 0603; SizeArea_mm2: 1.28; SizeAreaWB_mm2: 4.68; SizeX_mm: 1.6; SizeY_mm: 0.8; SizeZ_mm: 1; AEC Category: Q200; Green_Lifecycle: Active; Green_REACh: Passed
C50 = GRM155R70J105MA12D: CAP, CERM, 1 µF, 6.3 V,+/- 20%, X7R, 0402; Manufacturer: MuRata; Polarized: N; CompType: Capacitor; Value: 1uF; U/M: EA; Cap_F: 0.000001; Tolerance_%: 20; VDC_V: 6.3; Value2: 6.3V; TaMin_C: -55; TaMax_C: 125; Cap_Case: 0402; SizeArea_mm2: 0.5; SizeAreaWB_mm2: 3; SizeX_mm: 1; SizeZ_mm: 0.6; AEC Category: Q200
C51 = GRM155R70J223KA01D: CAP, CERM, 0.022 µF, 6.3 V, +/- 10%, X7R, 0402; Manufacturer: MuRata; Polarized: N; CompType: Capacitor; Value: 0.022uF; U/M: EA; Cap_F: 0.000000022; Tolerance_%: 10; Value1: Unknown; VDC_V: 6.3; Value2: 6.3V; TaMin_C: -55; TaMax_C: 125; Cap_Case: 0402; SizeArea_mm2: 0.5; SizeAreaWB_mm2: 3; SizeX_mm: 1; SizeZ_mm: 0.6; AEC Category: Q200
L9-L11 = BLM15AX102SN1D: Ferrite Bead, 1000 ohm @ 100 MHz, 0.35 A, 0402; Manufacturer: MuRata; Imax_A: 0.35; DCR_ohm: 0.49; Value1: 0.49 ohm; Value2: 0.35A; ZTyp@100MHz_Ohm: 1000
R8 R9 = CRCW04021K50JNED: RES, 1.5 k, 5%, 0.063 W, 0402; Manufacturer: Vishay-Dale; CompType: Resistor; Value: 1.5k; Res_ohm: 1500; Value_Code: 1k50; Tolerance_%: 5; Power_W: 0.063; Value2: 0.063W; VDC_V: 50; TempCo: 200 ppm/C; SizeArea_mm2: 0.5; SizeX_mm: 1; SizeZ_mm: 0.6; EIA_Code: E24; U/M: EA; AEC Category: Q200; Green_Lifecycle: Active; Green_REACh: Passed
R10 R13 = CRCW040210K0JNED: RES, 10k ohm, 5%, 0.063W, 0402; Manufacturer: Vishay-Dale; CompType: Resistor; Res_ohm: 10000; Value_Code: 10k0; Tolerance_%: 5; Power_W: 0.063; VDC_V: 50; TempCo: 200 ppm/C; EIA_Code: E24; U/M: EA
R11 = CRCW040249R9FKED: RES, 49.9 ohm, 1%, 0.063W, 0402; Manufacturer: Vishay-Dale; CompType: Resistor; Value_Code: 49R9; Tolerance_%: 1; Power_W: 0.063; VDC_V: 50; TempCo: 100 ppm/C; EIA_Code: E96; U/M: EA
R12 = CRCW04020000Z0ED: RES, 0, 5%, 0.063 W, 0402; Manufacturer: Vishay-Dale; CompType: Resistor; Value: 0; Value_Code: 0000; Tolerance_%: 5; Power_W: 0.063; Value2: 0.063W; VDC_V: 50; TempCo: 200 ppm/C; SizeArea_mm2: 0.5; SizeX_mm: 1; SizeZ_mm: 0.6; EIA_Code: E24; U/M: EA; AEC Category: Q200; Green_Lifecycle: Active; Green_REACh: Passed
R14 = CRCW040240K2FKED: RES, 40.2 k, 1%, 0.063 W, 0402; Manufacturer: Vishay-Dale; CompType: Resistor; Value: 40.2k; Res_ohm: 40200; Value_Code: 40k2; Tolerance_%: 1; Power_W: 0.063; Value2: 0.063W; VDC_V: 50; TempCo: 100 ppm/C; SizeArea_mm2: 0.5; SizeZ_mm: 0.6; EIA_Code: E96; U/M: EA; AEC Category: Q200; Green_Lifecycle: Active; Green_REACh: Passed
R15 = CRCW0402402RFKED: RES, 402, 1%, 0.063 W, 0402; Manufacturer: Vishay-Dale; CompType: Resistor; Value: 402; Value_Code: 402R; Tolerance_%: 1; Power_W: 0.063; Value2: 0.063W; VDC_V: 50; TempCo: 100 ppm/C; SizeArea_mm2: 0.5; SizeZ_mm: 0.6; EIA_Code: E96; U/M: EA; AEC Category: Q200
U5 = CMP-0084098-1: 2MP MIPI CSI-2 FPD-Link III Serializer for 2MP/60fps Cameras and RADAR, RHB0032P (VQFN-32); Manufacturer: Texas Instruments; Alternate PartNumber: DS90UB953TRHBTQ1; Rating: Automotive; SizeAreaWB_mm2: 49; SizeArea_mm2: 25; AEC Qualified: Y; AEC Category: Q200; SizeZ_mm: 1; SizeY_mm: 5; CompType: IC

## Sheet HDWR.SchDoc: Hardware
size 431 x 279 mm; Date: Not shown in title block; ApprovedBy: Not shown in title block; CheckedBy: Not shown in title block; Author: Not shown in title block; CompanyName: Not shown in title block; DrawnBy: Jeramie Bianchi; Engineer: Not shown in title block; Organization: Not shown in title block; Address1: Not shown in title block; Address2: Not shown in title block; Address3: Not shown in title block; Address4: Not shown in title block; DocumentNumber: 4; Revision: Use project parameter SCH_Rev; SheetNumber: 5; SheetTotal: 5; PageSetup: Record=PageOptions¦CenterHorizontal=True¦CenterVertical=True¦PrintScale=1.00¦XCorrection=1.00¦YCorrection=1.00¦PrintKind=0¦BorderSize=5000000¦LeftOffset=0¦BottomOffset=0¦Orientation=2¦PaperLength=1000¦PaperWidth=1000¦Scale=100¦PaperSource=15¦PrintQuality=600¦MediaType=1¦DitherType=10¦PaperKind=Letter¦PrintScaleMode=1
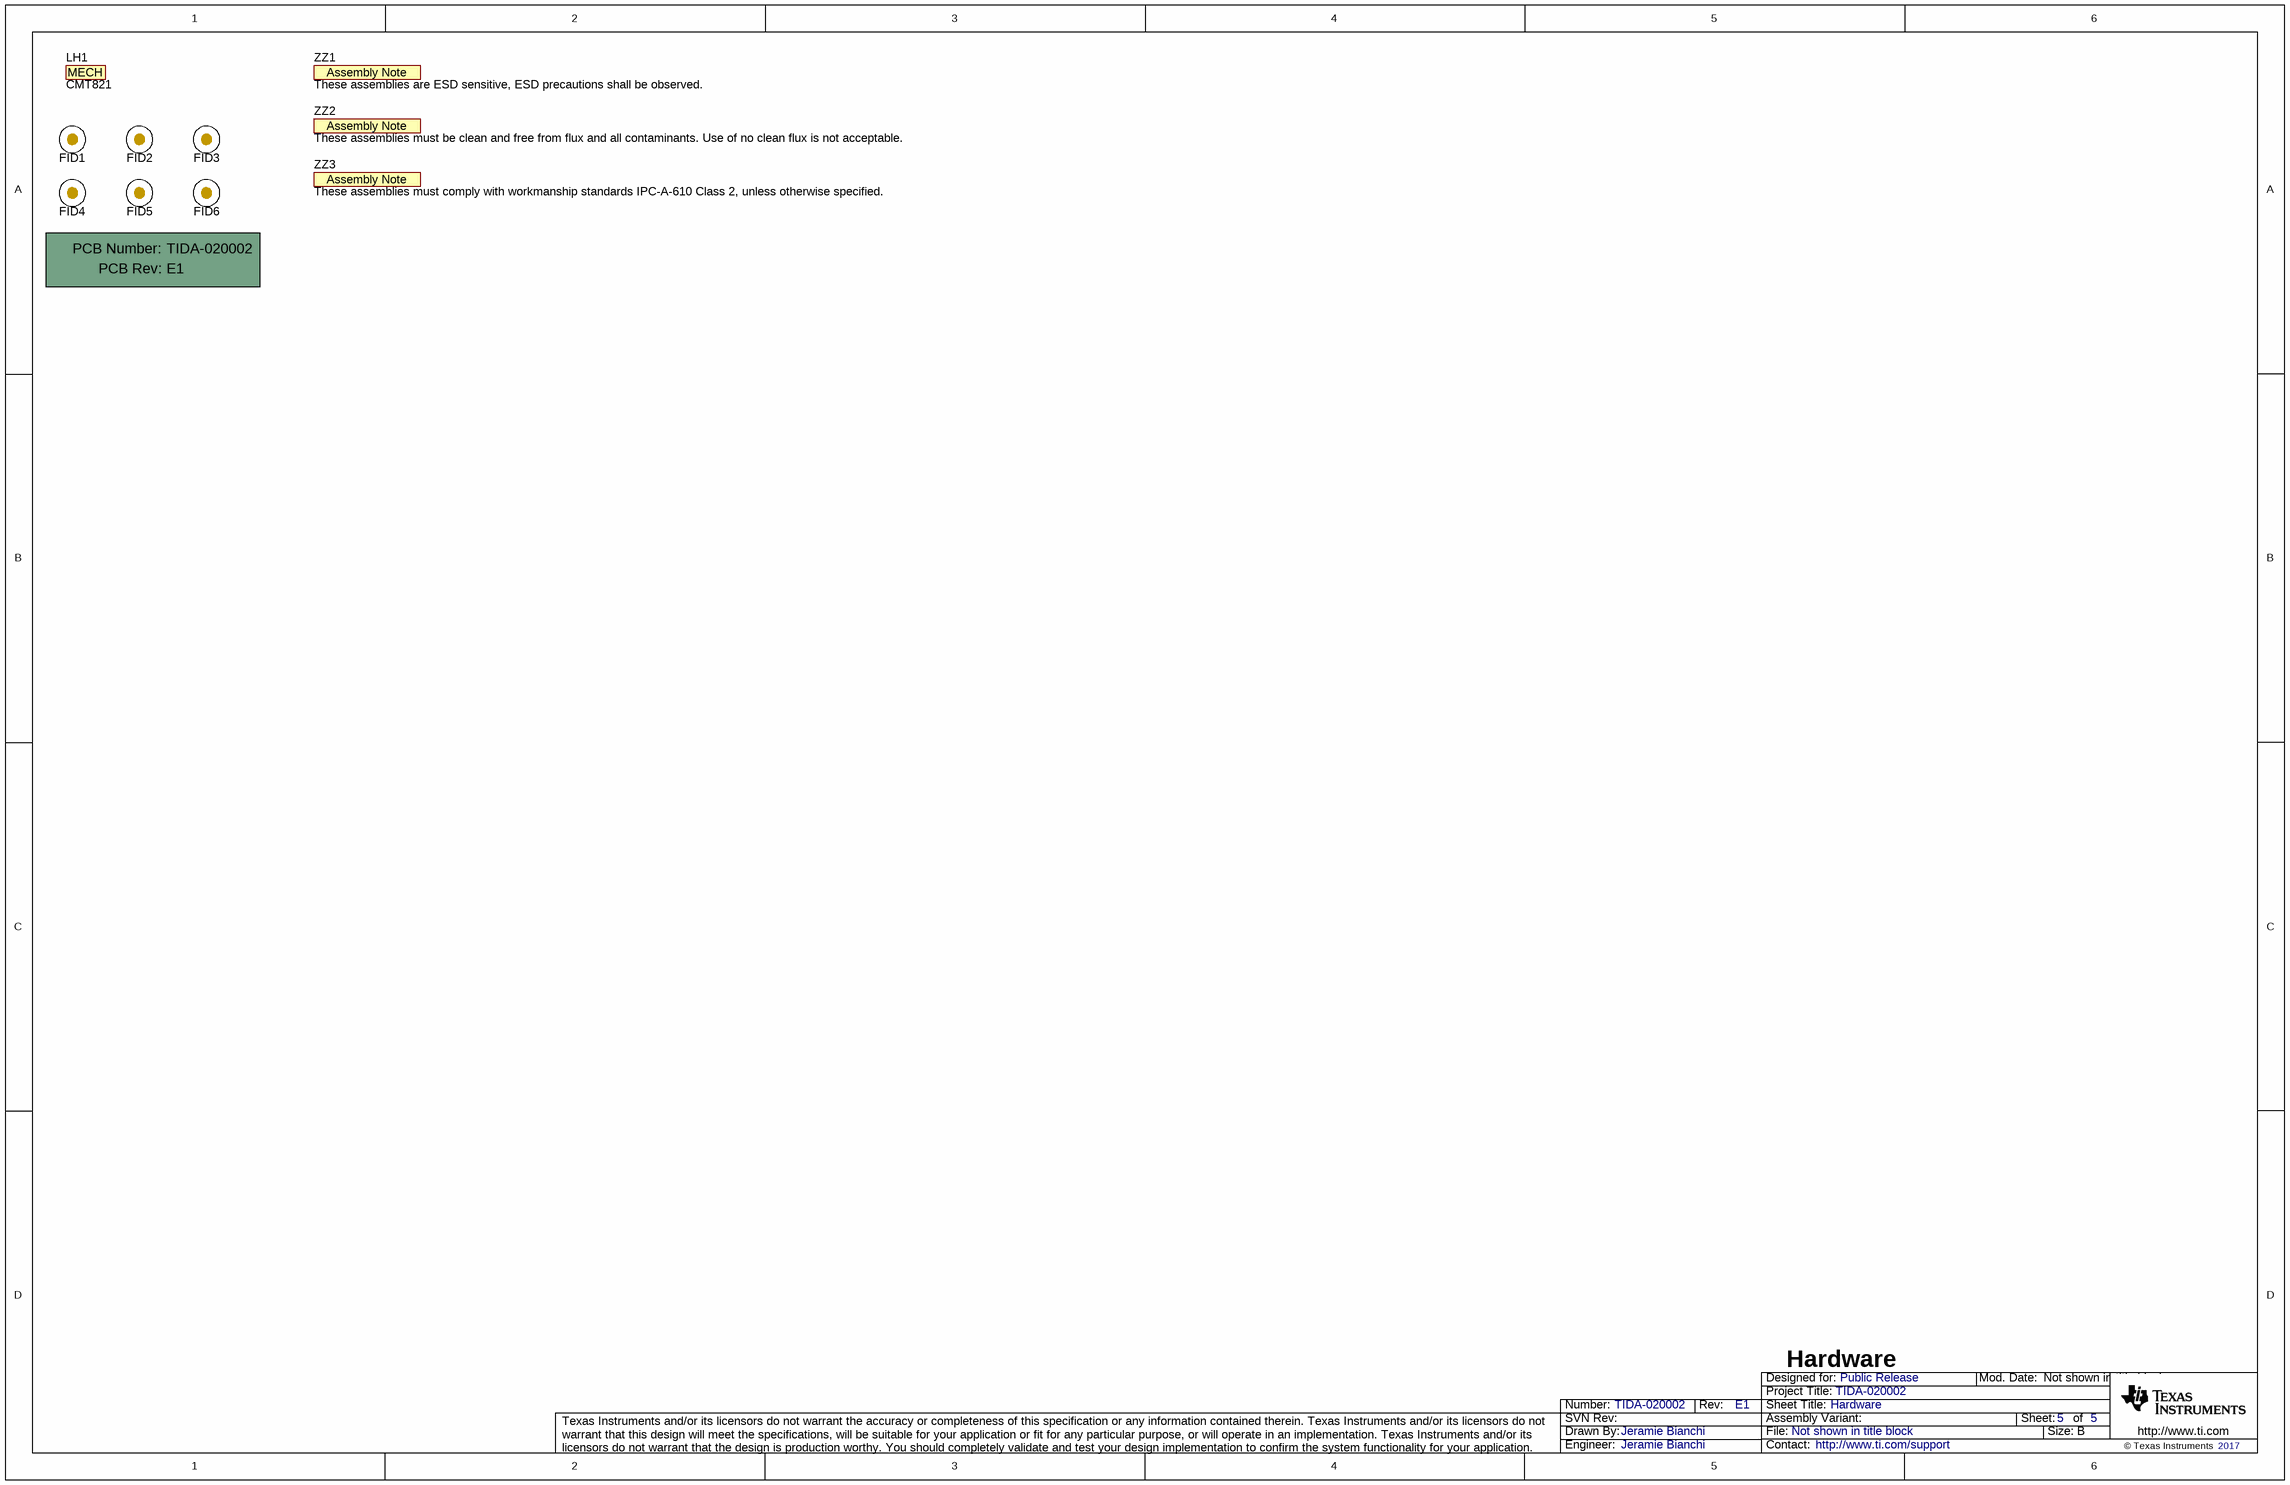
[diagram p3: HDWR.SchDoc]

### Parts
!PCB1  Printed Circuit Board  (value not drawn)  (mechanical)
FID1  Fiducial  [Fiducial10-20]  (value not drawn)
FID2  Fiducial  [Fiducial10-20]  (value not drawn)
FID3  Fiducial  [Fiducial10-20]  (value not drawn)
FID4  Fiducial  [Fiducial10-20]  (value not drawn)
FID5  Fiducial  [Fiducial10-20]  (value not drawn)
FID6  Fiducial  [Fiducial10-20]  (value not drawn)
LH1  CMT821  [CMT821]
ZZ1  These assemblies are ESD sensitive, ESD precautions shall be observed.  [AssemblyNote]  (no BOM)
ZZ2  These assemblies must be clean and free from flux and all contaminants. Use of no clean flux is not acceptable.  [AssemblyNote]  (no BOM)
ZZ3  These assemblies must comply with workmanship standards IPC-A-610 Class 2, unless otherwise specified.  [AssemblyNote]  (no BOM)

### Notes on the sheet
- Hardware

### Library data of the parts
!PCB1 = PCB: Manufacturer: Any; PartNumber: TIDA-020002; SymbolCreator: a0412235
FID1-FID6 = Fiducial: Fiducial mark.  There is nothing to buy or mount.; SymbolCreator: codlsc
LH1 = CMT821: Sunex Lens Holder; Manufacturer: Sunex Inc.
ZZ1-ZZ3 = AssemblyNote: SymbolCreator: codlsc

## Sheet Voltage Supervision.SchDoc: Voltage Supervision
size 431 x 279 mm; Date: Not shown in title block; ApprovedBy: Not shown in title block; CheckedBy: Not shown in title block; Author: Not shown in title block; CompanyName: Not shown in title block; DrawnBy: Jeramie Bianchi; Engineer: Not shown in title block; Organization: Not shown in title block; Address1: Not shown in title block; Address2: Not shown in title block; Address3: Not shown in title block; Address4: Not shown in title block; DocumentNumber: 1; Revision: Use project parameter SCH_Rev; SheetNumber: 2; SheetTotal: 5; PageSetup: Record=PageOptions¦CenterHorizontal=True¦CenterVertical=True¦PrintScale=1.00¦XCorrection=1.00¦YCorrection=1.00¦PrintKind=0¦BorderSize=5000000¦LeftOffset=0¦BottomOffset=0¦Orientation=2¦PaperLength=1000¦PaperWidth=1000¦Scale=100¦PaperSource=15¦PrintQuality=600¦MediaType=1¦DitherType=10¦PaperKind=Letter¦PrintScaleMode=1
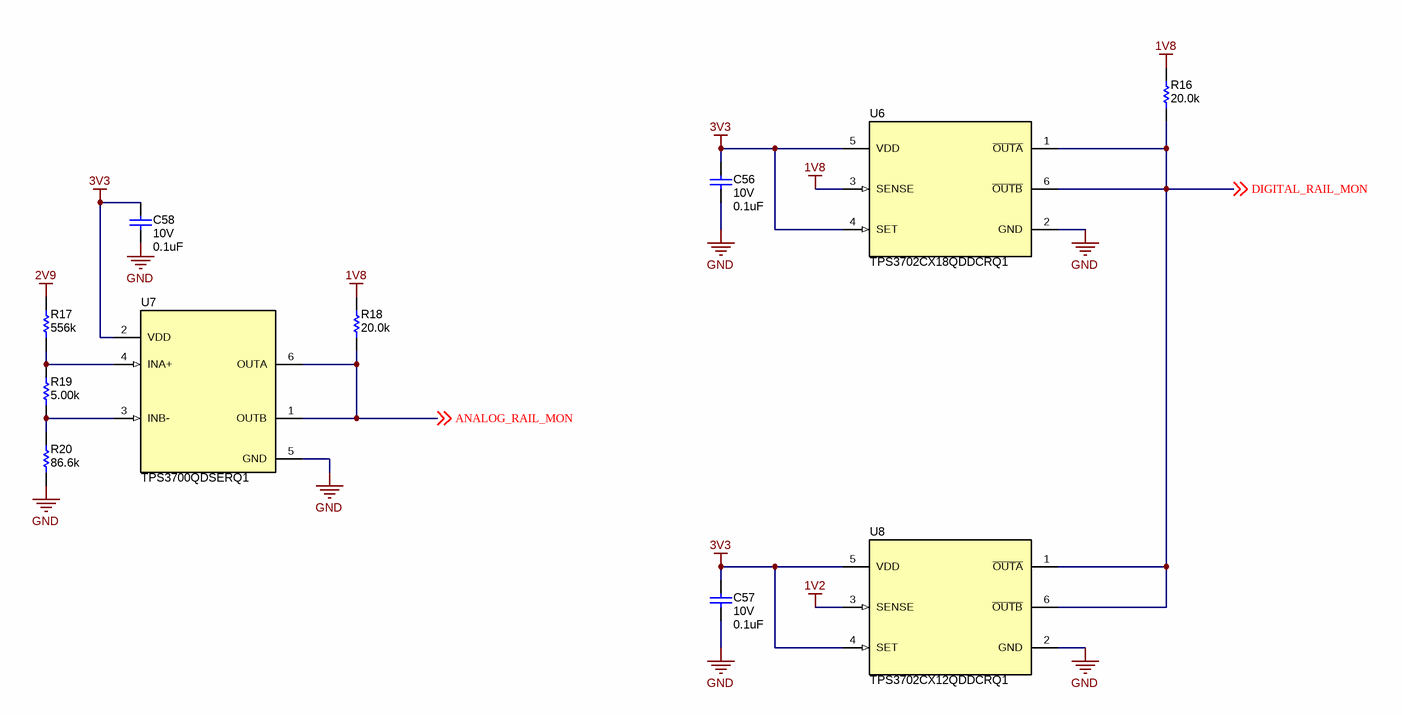
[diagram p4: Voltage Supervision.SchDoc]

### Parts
C56  VDC_V: 10V  ValueDisplayed: 0.1uF  [0402S]  (hidden comment: GRM155R71A104KA01D)
C57  VDC_V: 10V  ValueDisplayed: 0.1uF  [0402S]  (hidden comment: GRM155R71A104KA01D)
C58  VDC_V: 10V  ValueDisplayed: 0.1uF  [0402S]  (hidden comment: GRM155R71A104KA01D)
R16  ValueDisplayed: 20.0k  [0402S]  (hidden comment: CRCW040220K0FKED)
R17  ValueDisplayed: 556k  [0603S]  (hidden comment: RT0603BRD07556KL)
R18  ValueDisplayed: 20.0k  [0402S]  (hidden comment: CRCW040220K0FKED)
R19  ValueDisplayed: 5.00k  [0402S]  (hidden comment: PNM0402E5001BST1)
R20  ValueDisplayed: 86.6k  [0402S]  (hidden comment: ERA-2AEB8662X)
U6  TPS3702CX18QDDCRQ1  [DDC0006A_N]
U7  TPS3700QDSERQ1  [DSE0006A]
U8  TPS3702CX12QDDCRQ1  [DDC0006A_N]

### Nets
1V2: U8.3(SENSE)
1V8: R16.2 R18.2 U6.3(SENSE)
2V9: R17.2
3V3: C56.1 C57.1 C58.1 U6.4(SET) U6.5(VDD) U7.2(VDD) U8.4(SET) U8.5(VDD)
GND: C56.2 C57.2 C58.2 R20.1 U6.2(GND) U7.5(GND) U8.2(GND)
ANALOG_RAIL_MON: R18.1 U7.1(OUTB) U7.6(OUTA) ; off-sheet ANALOG_RAIL_MON
DIGITAL_RAIL_MON: R16.1 U6.1(~{OUTA}) U6.6(~{OUTB}) U8.1(~{OUTA}) U8.6(~{OUTB}) ; off-sheet DIGITAL_RAIL_MON
NetR17_1: R17.1 R19.2 U7.4(INA+)
NetR19_1: R19.1 R20.2 U7.3(INB-)

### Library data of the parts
C56-C58 = CMP-0006629-2: CAP, CERM, 0.1 uF, 10 V, +/- 10%, X7R, 0402; Manufacturer: MuRata; TaMin_C: -55°C; Polarized: N; SizeAreaWB_mm2: 3; Value1: Unknown; U/M: EA; Value: 0.1uF; TaMax_C: 125°C; SizeZ_mm: 0.6; SizeX_mm: 1; SizeY_mm: 0.5; Cap_Case: 0402; CompType: Capacitor; Cap_F: 100nF; AEC Category: Q200
R16 R18 = CMP-0026162-2: RES, 20.0 k, 1%, 0.063 W, AEC-Q200 Grade 0, 0402; Manufacturer: Vishay-Dale; Power_W: 63mW; TempCo: 100 ppm/C; Value_Code: 20k0; Value: 20.0k; EIA_Code: E96; Res_ohm: 20k; SizeX_mm: 1; SizeY_mm: 0.5; SizeZ_mm: 0.6; Value2: 0.063W; CompType: Resistor; AEC Qualified: Y; VDC_V: 50V; AEC Category: Q200; AEC Grade: 0
R17 = CMP-0024337-2: RES, 556 k, 0.1%, 0.1 W, 0603; Manufacturer: Yageo America; Power_W: 100mW; TempCo: 25 ppm/C; U/M: EA; Value: 556k; EIA_Code: E192; SizeX_mm: 1.6; SizeY_mm: 0.8; SizeZ_mm: 1; Value2: 0.1W; SizeArea_mm2: 1.28; CompType: Resistor; VDC_V: 75V; AEC Category: Q200
R19 = CMP-0026813-1: RES, 5.00 k, 0.1%, 0.05 W, 0402; Manufacturer: Vishay-Dale; Power_W: 50mW; TempCo: 25 ppm/C; Value_Code: 5k00; U/M: EA; Value: 5.00k; Res_ohm: 5k; SizeX_mm: 1; SizeY_mm: 0.5; SizeZ_mm: 0.6; Value2: 0.05W; CompType: Resistor; AEC Qualified: N; VDC_V: 75V; AEC Category: Q200
R20 = CMP-0026789-1: RES, 86.6 k, 0.1%, 0.063 W, AEC-Q200 Grade 0, 0402; Manufacturer: Panasonic; Power_W: 63mW; TempCo: 25 ppm/C; Value_Code: 86k6; U/M: EA; Value: 86.6k; EIA_Code: E192; SizeX_mm: 1; SizeY_mm: 0.5; SizeZ_mm: 0.6; Value2: 0.063W; CompType: Resistor; AEC Qualified: Y; VDC_V: 50V; AEC Grade: 0; AEC Category: Q200
U6 U8 = CMP-0067338-2: High-Accuracy, Fixed-Threshold OV/UV Monitor for Automotive, DDC0006A (SOT-23-T-6); Manufacturer: Texas Instruments; SizeZ_mm: 0.87; SizeX_mm: 1.65; SizeY_mm: 2.95; SizeArea_mm2: 4.8675; CompType: IC; U/M: EA; SizeAreaWB_mm2: 10.4675
U7 = CMP-0084096-1: Automotive, High-Voltage (18V) Window Comparator with Over- and Undervoltage Detection, DSE0006A (WSON-6); Manufacturer: Texas Instruments; SizeAreaWB_mm2: 6.25; SizeArea_mm2: 2.25; AEC Qualified: Y; AEC Category: Q200; SizeZ_mm: 0.8; SizeY_mm: 1.5; CompType: IC

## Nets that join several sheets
1V2: Coax Connection and Power Supply (C8.1 L7.2 U2.4), Imager (19 pins), Voltage Supervision (U8.3)
1V8: Coax Connection and Power Supply (C9.1 L8.2 U2.1), Imager (6 pins), Serializer (L9.1 L10.1 L11.1), Voltage Supervision (R16.2 R18.2 U6.3)
2V9: Coax Connection and Power Supply (C7.1 U3.1), Imager (18 pins), Voltage Supervision (R17.2)
3V3: Coax Connection and Power Supply (9 pins), Voltage Supervision (8 pins)
GND: Coax Connection and Power Supply (22 pins), Imager (66 pins), Serializer (22 pins), Voltage Supervision (7 pins)
ANALOG_RAIL_MON: Serializer (U5.28), Voltage Supervision (R18.1 U7.1 U7.6)
CSI0_CLK_N: Imager (U4.D2), Serializer (U5.6)
CSI0_CLK_P: Imager (U4.D1), Serializer (U5.5)
CSI0_D0_N: Imager (U4.E2), Serializer (U5.4)
CSI0_D0_P: Imager (U4.E1), Serializer (U5.3)
CSI0_D1_N: Imager (U4.C2), Serializer (U5.2)
CSI0_D1_P: Imager (U4.C1), Serializer (U5.1)
CSI0_D2_N: Imager (U4.F2), Serializer (U5.32)
CSI0_D2_P: Imager (U4.F1), Serializer (U5.31)
CSI0_D3_N: Imager (U4.B2), Serializer (U5.30)
CSI0_D3_P: Imager (U4.B1), Serializer (U5.29)
DIGITAL_RAIL_MON: Serializer (U5.27), Voltage Supervision (5 pins)
DOUTP_F: Coax Connection and Power Supply (J1.1 L2.1), Serializer (C40.1)
FSIN: Imager (U4.L6), Serializer (U5.18)
SCL: Imager (U4.L10), Serializer (R8.1 U5.24)
SDA: Imager (U4.L9), Serializer (R9.1 U5.23)
SYS_CLEAR: Imager (U4.J2), Serializer (U5.17)
XCLK: Imager (U4.J1), Serializer (R12.1 R14.2 U5.19)

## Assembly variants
001: not fitted FID1 FID2 FID3 FID4 FID5 FID6 L7 R13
